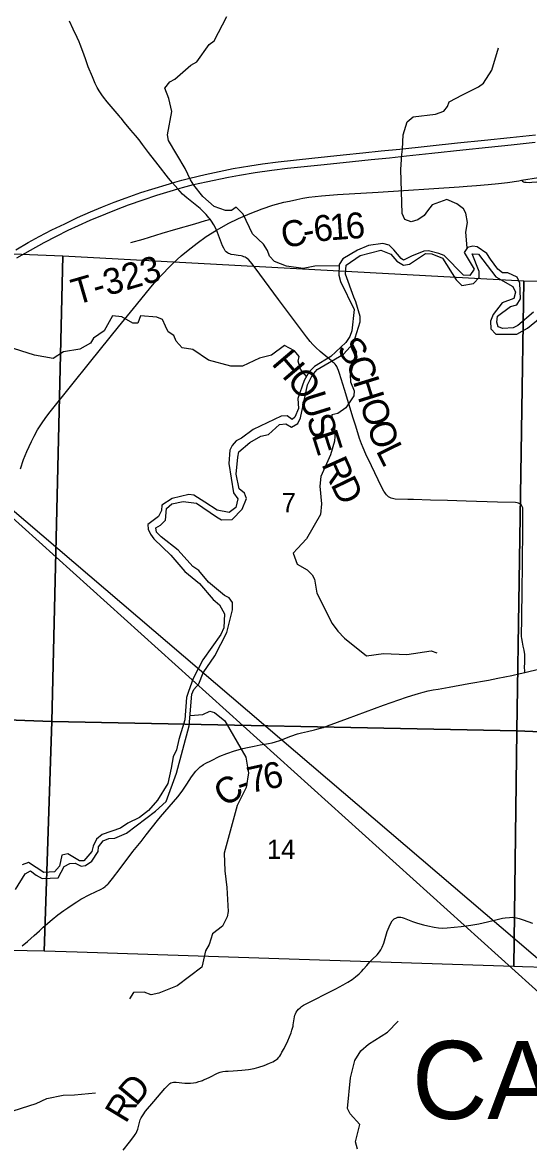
# Model space of a CAD drawing. Extents: x 0 to 34, y 0 to 22.
# Drawn here: x 6.991 to 8.096, y 18.295 to 20.748 of the extents above; entities that cross this region are included whole.
import ezdxf

# ---------------------------------------------------------------- set-up
doc = ezdxf.new("R2010")
doc.units = 0
for name, color, linetype in [('GM_X_County_Road', 7, 'Continuous'), ('GM_X_County_Road_Text', 7, 'Continuous'), ('GM_X_Minor_River', 7, 'Continuous'), ('GM_X_Section', 7, 'Continuous'), ('GM_X_Section_Text', 7, 'Continuous'), ('GM_X_State_Route', 7, 'Continuous'), ('GM_X_Township_Road', 7, 'Continuous'), ('GM_X_Township_Road_Text', 7, 'Continuous'), ('GM_X_Township_Text', 7, 'Continuous'), ('SH_Data', 7, 'Continuous')]:
    doc.layers.add(name, color=color, linetype=linetype)

msp = doc.modelspace()

# ---------------------------------------------------------------- linework, layer by layer
at = {"layer": 'GM_X_County_Road'}
for points in [[(8.0813, 20.4027), (8.1179, 20.4089), (8.2717, 20.437)], [(7.4149, 20.2934), (7.4164, 20.2943), (7.4408, 20.308), (7.463, 20.319), (7.4885, 20.3302), (7.5146, 20.3403), (7.5381, 20.348), (7.5621, 20.3545), (7.5743, 20.3574), (7.5902, 20.3608), (7.6034, 20.3633), (7.6168, 20.3655), (7.6445, 20.3688), (7.6789, 20.3714), (7.768, 20.3769), (7.9451, 20.3883), (7.9621, 20.3895), (7.9824, 20.391), (8.0083, 20.3934), (8.0305, 20.3958), (8.0504, 20.3982), (8.075, 20.4016), (8.0813, 20.4027)], [(6.9871, 19.7721), (6.9939, 19.7927), (7.0007, 19.81), (7.0108, 19.8316), (7.017, 19.8436), (7.0246, 19.8575), (7.0328, 19.8706), (7.0427, 19.8843), (7.0518, 19.8967), (7.1409, 20.0073), (7.2011, 20.0825), (7.2405, 20.1305), (7.2719, 20.169), (7.288, 20.1878), (7.2986, 20.1992), (7.31, 20.2112), (7.3199, 20.2208), (7.3294, 20.2298), (7.3378, 20.2372), (7.3457, 20.2441), (7.3594, 20.2549), (7.3726, 20.2651), (7.3928, 20.2795), (7.4149, 20.2934)], [(6.991, 18.7293), (7.0024, 18.7392), (7.0173, 18.7522), (7.0285, 18.7626), (7.0369, 18.7701), (7.0559, 18.7869), (7.0684, 18.7973), (7.0816, 18.8069), (7.0904, 18.8129), (7.1001, 18.8191), (7.11, 18.8255), (7.119, 18.8312), (7.1382, 18.8414), (7.1633, 18.8536), (7.1681, 18.8565), (7.1717, 18.8589), (7.1745, 18.8613), (7.1775, 18.8643), (7.1792, 18.8661), (7.1878, 18.8764), (7.2049, 18.8985), (7.2327, 18.9359), (7.2503, 18.9576), (7.2617, 18.9719), (7.2863, 19.0037), (7.2929, 19.0117), (7.3023, 19.0227), (7.331, 19.0554), (7.3404, 19.0676), (7.3506, 19.0831), (7.3607, 19.0988), (7.37, 19.1113), (7.3726, 19.1144), (7.3765, 19.1181), (7.3795, 19.1208), (7.3838, 19.124), (7.3869, 19.126), (7.3918, 19.1288), (7.4028, 19.1342), (7.4226, 19.1437), (7.4376, 19.15), (7.4545, 19.156), (7.4725, 19.1609), (7.4826, 19.1633), (7.497, 19.166), (7.5105, 19.1685), (7.5285, 19.1717), (7.5363, 19.1734), (7.544, 19.1754), (7.5531, 19.1785), (7.577, 19.1879), (7.5917, 19.1927), (7.6008, 19.1953), (7.6134, 19.1983), (7.629, 19.2016), (7.6338, 19.2028), (7.6419, 19.2049), (7.6485, 19.207), (7.6577, 19.21), (7.7013, 19.2263), (7.7799, 19.2553), (7.8297, 19.2727), (7.8415, 19.2766), (7.8564, 19.2811), (7.8661, 19.2838), (7.8775, 19.2865), (7.8879, 19.2888), (7.8989, 19.2907), (7.9234, 19.2948), (7.9661, 19.3026), (8.0088, 19.3105), (8.029, 19.3145), (8.0601, 19.3207), (8.078, 19.3248), (8.0885, 19.3272)], [(8.0885, 19.3272), (8.1209, 19.3346)]]:
    msp.add_lwpolyline(points, dxfattribs=at)
at = {"layer": 'GM_X_Minor_River'}
for points in [[(7.683, 20.2154), (7.6294, 20.2153), (7.6044, 20.2099), (7.5677, 20.2147), (7.5416, 20.2252), (7.5305, 20.2366), (7.5263, 20.2491), (7.5179, 20.2627), (7.4936, 20.2857), (7.473, 20.3285), (7.4581, 20.3437), (7.4476, 20.3364), (7.4347, 20.3367), (7.4101, 20.3454), (7.385, 20.3669), (7.3659, 20.3923), (7.358, 20.404), (7.3465, 20.4286), (7.3103, 20.4896), (7.3083, 20.5021), (7.3176, 20.5533), (7.311, 20.5814), (7.3022, 20.6037), (7.3135, 20.6182), (7.3244, 20.6239), (7.3591, 20.6544), (7.3724, 20.6613), (7.3994, 20.6993), (7.41, 20.7073), (7.4374, 20.7605)], [(7.9627, 20.255), (7.9595, 20.289), (7.9628, 20.3102), (7.9594, 20.3307), (7.954, 20.3405), (7.94, 20.3515), (7.9183, 20.3609), (7.8858, 20.349), (7.8761, 20.3361), (7.8685, 20.3254), (7.8549, 20.3163), (7.8402, 20.3121), (7.8266, 20.3173), (7.8204, 20.3302), (7.8174, 20.4265), (7.8199, 20.4592), (7.821, 20.4706), (7.8227, 20.5017), (7.8313, 20.5302), (7.8445, 20.5416), (7.8929, 20.5471), (7.9111, 20.5536), (7.9194, 20.5639), (7.9231, 20.5741), (7.9522, 20.5898), (7.9869, 20.607), (7.9982, 20.615), (8.0163, 20.6435), (8.0305, 20.6921)], [(8.1071, 20.1146), (8.0728, 20.0853), (8.063, 20.0803), (8.0403, 20.0787), (8.0304, 20.0821), (8.027, 20.0923), (8.0288, 20.106), (8.0567, 20.127), (8.0711, 20.1304), (8.079, 20.1434), (8.077, 20.1779), (8.0716, 20.1911), (8.0508, 20.2002), (8.0398, 20.2005), (8.0291, 20.2084), (8.0135, 20.2304), (8.0055, 20.2425), (7.9843, 20.2572), (7.9748, 20.2587), (7.9631, 20.2556), (7.9559, 20.2446), (7.9773, 20.2082), (7.9683, 20.1949), (7.9546, 20.1952), (7.9121, 20.2383), (7.9007, 20.2425), (7.8776, 20.2488), (7.8677, 20.248), (7.8405, 20.2369), (7.8236, 20.2279), (7.818, 20.2317), (7.8026, 20.2505), (7.792, 20.2607), (7.778, 20.2644), (7.7466, 20.2605), (7.7228, 20.2498)], [(6.9763, 18.8525), (6.9973, 18.8871), (7.0087, 18.8936), (7.0216, 18.8837), (7.0341, 18.8766), (7.0694, 18.8785), (7.0824, 18.9029), (7.0949, 18.9098), (7.1063, 18.9102), (7.1195, 18.9034), (7.1294, 18.9054), (7.1426, 18.9149), (7.1569, 18.9354), (7.1576, 18.9457), (7.1674, 18.959), (7.1802, 18.9643), (7.1931, 18.9648), (7.2184, 18.9759), (7.2822, 19.0235), (7.3055, 19.0448), (7.328, 19.1068), (7.3555, 19.2101), (7.3609, 19.2795), (7.3654, 19.2901), (7.3763, 19.3023), (7.3857, 19.3263), (7.4117, 19.3632), (7.4379, 19.4141), (7.4502, 19.4638), (7.4501, 19.4798), (7.4425, 19.49), (7.4323, 19.4953), (7.3977, 19.5247), (7.3768, 19.5497), (7.3635, 19.5584), (7.3316, 19.5943), (7.2939, 19.6237), (7.2841, 19.6336), (7.2825, 19.6434), (7.2931, 19.6488), (7.304, 19.6595), (7.3062, 19.6856), (7.3175, 19.6955), (7.3421, 19.7006), (7.3712, 19.6969), (7.4149, 19.6674), (7.4263, 19.6606), (7.449, 19.6611), (7.4708, 19.6836), (7.4806, 19.7075), (7.476, 19.7185), (7.4642, 19.7283), (7.458, 19.7602), (7.462, 19.7974), (7.4635, 19.8091), (7.488, 19.8293), (7.5118, 19.8434), (7.5284, 19.8473), (7.5529, 19.8686), (7.5662, 19.8702), (7.5787, 19.863), (7.593, 19.8711), (7.5987, 19.8836), (7.6135, 19.9555), (7.6241, 19.9763), (7.6347, 19.9892), (7.6927, 20.0228), (7.7142, 20.0464), (7.7287, 20.0935), (7.7287, 20.1049), (7.7195, 20.1367), (7.7152, 20.1469), (7.6965, 20.1977), (7.6983, 20.2171), (7.7285, 20.2384), (7.7739, 20.2496), (7.7955, 20.2413), (7.8088, 20.2262), (7.8236, 20.2168)], [(6.9763, 18.8525), (6.9973, 18.8871), (7.0087, 18.8936), (7.0216, 18.8837), (7.0341, 18.8766), (7.0694, 18.8785), (7.0824, 18.9029), (7.0949, 18.9098), (7.1063, 18.9102), (7.1195, 18.9034), (7.1294, 18.9054), (7.1426, 18.9149), (7.1569, 18.9354), (7.1576, 18.9457), (7.1674, 18.959), (7.1802, 18.9643), (7.1931, 18.9648), (7.2184, 18.9759), (7.2822, 19.0235), (7.3055, 19.0448), (7.328, 19.1068), (7.3555, 19.2101), (7.3609, 19.2795), (7.3654, 19.2901), (7.3763, 19.3023), (7.3857, 19.3263), (7.4117, 19.3632), (7.4379, 19.4141), (7.4502, 19.4638), (7.4501, 19.4798), (7.4425, 19.49), (7.4323, 19.4953), (7.3977, 19.5247), (7.3768, 19.5497), (7.3635, 19.5584), (7.3316, 19.5943), (7.2939, 19.6237), (7.2841, 19.6336), (7.2825, 19.6434), (7.2931, 19.6488), (7.304, 19.6595), (7.3062, 19.6856), (7.3175, 19.6955), (7.3421, 19.7006), (7.3712, 19.6969), (7.4149, 19.6674), (7.4263, 19.6606), (7.449, 19.6611), (7.4708, 19.6836), (7.4806, 19.7075), (7.476, 19.7185), (7.4642, 19.7283), (7.458, 19.7602), (7.462, 19.7974), (7.4635, 19.8091), (7.488, 19.8293), (7.5118, 19.8434), (7.5284, 19.8473), (7.5529, 19.8686), (7.5662, 19.8702), (7.5787, 19.863), (7.593, 19.8711), (7.5987, 19.8836), (7.6135, 19.9555), (7.6241, 19.9763), (7.6347, 19.9892), (7.6927, 20.0228), (7.7142, 20.0464), (7.7287, 20.0935), (7.7287, 20.1049), (7.7195, 20.1367), (7.7152, 20.1469), (7.6965, 20.1977), (7.6983, 20.2171), (7.7285, 20.2384), (7.7739, 20.2496), (7.7955, 20.2413), (7.8088, 20.2262), (7.8236, 20.2168)], [(7.7228, 20.2498), (7.6907, 20.2311), (7.6831, 20.2189), (7.6821, 20.1954), (7.6856, 20.1814), (7.7154, 20.12), (7.7106, 20.0733), (7.7065, 20.0615), (7.6971, 20.0479), (7.6646, 20.0174), (7.6292, 19.9956), (7.6172, 19.9842), (7.6063, 19.9648), (7.5924, 19.9257), (7.594, 19.9041), (7.5862, 19.885), (7.5801, 19.8801), (7.5691, 19.888), (7.5563, 19.8869), (7.4954, 19.8582), (7.4698, 19.8387), (7.4581, 19.8334), (7.4494, 19.8231), (7.4442, 19.8128), (7.442, 19.7836), (7.4521, 19.7195), (7.4617, 19.7063), (7.4572, 19.6873), (7.4429, 19.6766), (7.4163, 19.6815), (7.3894, 19.6992), (7.3655, 19.7143), (7.3545, 19.7162), (7.3182, 19.7073), (7.2959, 19.6928), (7.2948, 19.681), (7.2885, 19.6681), (7.2654, 19.6502), (7.2659, 19.64), (7.2708, 19.6294), (7.2781, 19.6188), (7.3157, 19.5836), (7.3458, 19.5473), (7.3777, 19.5216), (7.4077, 19.4864), (7.4214, 19.4751), (7.4325, 19.4554), (7.4311, 19.4243), (7.4247, 19.4102), (7.3852, 19.3547), (7.3638, 19.3137), (7.3537, 19.2855), (7.3492, 19.2726), (7.346, 19.2233), (7.3326, 19.1805), (7.3278, 19.1576), (7.3204, 19.1427), (7.3158, 19.1177), (7.3088, 19.0843), (7.2866, 19.0482), (7.2666, 19.025), (7.247, 19.0097), (7.2213, 18.9979), (7.2055, 18.9868), (7.1654, 18.973), (7.153, 18.9624), (7.1455, 18.9471), (7.1429, 18.9354), (7.1255, 18.9152), (7.1163, 18.9152), (7.0903, 18.9306), (7.0774, 18.9276), (7.0726, 18.904), (7.0613, 18.8911), (7.0378, 18.8895), (7.0044, 18.9117), (6.9908, 18.9068)], [(7.8236, 20.2168), (7.8361, 20.2191), (7.8712, 20.2424), (7.8855, 20.2417), (7.9083, 20.2323), (7.938, 20.1849), (7.9509, 20.1729), (7.9763, 20.1771), (7.9883, 20.1904), (7.9887, 20.203), (7.9734, 20.242), (7.9874, 20.2409), (8.0251, 20.1917), (8.0622, 20.1706), (8.068, 20.1581), (8.0642, 20.1444), (8.0385, 20.1352), (8.019, 20.109), (8.0134, 20.0949), (8.0138, 20.0779), (8.0248, 20.0665), (8.0706, 20.0667), (8.0941, 20.0793), (8.122, 20.1022)], [(7.6114, 19.974), (7.5982, 19.9898), (7.5932, 20.0073), (7.5958, 20.0179), (7.5855, 20.03), (7.5635, 20.0417), (7.5349, 20.0207), (7.5092, 20.0142), (7.4718, 19.9966), (7.4464, 19.9961), (7.3975, 20.0092), (7.3637, 20.0326), (7.3399, 20.0367), (7.3273, 20.0511), (7.322, 20.0632), (7.3098, 20.0715), (7.3037, 20.084), (7.2968, 20.0984), (7.2847, 20.1033), (7.2491, 20.1062), (7.2431, 20.0906), (7.2325, 20.0902), (7.2082, 20.1041), (7.1881, 20.1067), (7.1701, 20.074), (7.1463, 20.0576), (7.1396, 20.047), (7.1165, 20.0336), (7.081, 20.0278), (7.0587, 20.0129), (7.0178, 20.0208), (6.9583, 20.0391)], [(7.7123, 20.0443), (7.7206, 20.0277), (7.7068, 19.9768), (7.708, 19.962), (7.7157, 19.9424), (7.7146, 19.9314), (7.6973, 19.9055), (7.6799, 19.8933), (7.667, 19.8902), (7.6678, 19.8803), (7.6744, 19.853), (7.673, 19.8325), (7.664, 19.8025), (7.643, 19.7554), (7.6408, 19.7341), (7.6441, 19.6958), (7.6423, 19.6719), (7.6114, 19.6187), (7.5918, 19.5981), (7.5828, 19.5874), (7.5912, 19.5636), (7.6129, 19.5515), (7.6243, 19.5406), (7.6293, 19.5307), (7.634, 19.5004), (7.6676, 19.4338), (7.6798, 19.4171), (7.6947, 19.4017), (7.7426, 19.3632), (7.7797, 19.3683), (7.8309, 19.3666), (7.8835, 19.3745), (7.8964, 19.3696)], [(7.3573, 19.2326), (7.3854, 19.2348), (7.4002, 19.2421), (7.4104, 19.2395), (7.4336, 19.221), (7.4791, 19.1416), (7.483, 19.1203), (7.4849, 19.1074), (7.4798, 19.0755), (7.4603, 19.036), (7.4319, 18.9323), (7.4329, 18.8936), (7.4376, 18.8568), (7.4405, 18.8049), (7.4386, 18.7931), (7.4285, 18.7722), (7.4062, 18.7554), (7.3991, 18.7322), (7.3908, 18.7189), (7.3849, 18.6927), (7.3827, 18.6832)], [(7.3827, 18.6832), (7.3294, 18.642), (7.2893, 18.6263), (7.2723, 18.6228), (7.2571, 18.628), (7.234, 18.6272), (7.2253, 18.6138)], [(7.7226, 18.2849), (7.7183, 18.3008), (7.728, 18.3392), (7.7071, 18.3622), (7.7013, 18.374), (7.7078, 18.4408), (7.7171, 18.4788), (7.7299, 18.4997), (7.7469, 18.5146), (7.7885, 18.5406), (7.8119, 18.5649)], [(6.3977, 18.2296), (6.4186, 18.2279), (6.4369, 18.2086), (6.4495, 18.1836), (6.4761, 18.1773), (6.547, 18.1723), (6.5572, 18.1724), (6.5992, 18.1968), (6.6211, 18.217), (6.644, 18.2543), (6.6758, 18.2768), (6.7268, 18.3032), (6.7793, 18.3399), (6.8243, 18.3659), (6.8701, 18.374), (6.9066, 18.3628), (6.9191, 18.3613), (6.9551, 18.3638), (7.0213, 18.3846), (7.0444, 18.396), (7.0804, 18.403), (7.105, 18.4039), (7.1512, 18.4086)]]:
    msp.add_lwpolyline(points, dxfattribs=at)
at = {"layer": 'GM_X_Section'}
for points in [[(6.1908, 20.2736), (7.0795, 20.2374), (7.0553, 19.2199), (6.1559, 19.253), (6.1718, 19.7471), (6.1903, 20.2549), (6.1905, 20.2588)], [(7.0795, 20.2374), (8.0858, 20.1828), (8.0709, 19.1994), (7.0553, 19.2199)], [(8.0858, 20.1828), (8.5906, 20.172), (8.5904, 20.1552), (8.5847, 19.6569), (8.5803, 19.1784), (8.0709, 19.1994)], [(6.1559, 19.253), (7.0553, 19.2199), (7.0388, 18.7177), (6.6277, 18.7256), (6.1384, 18.7353), (6.1557, 19.2472)], [(7.0553, 19.2199), (8.0709, 19.1994), (8.0639, 18.6844), (7.5959, 18.6998), (7.1106, 18.7154), (7.0388, 18.7177)], [(8.0709, 19.1994), (8.5803, 19.1784), (8.5708, 18.6694), (8.083, 18.6836), (8.0639, 18.6844)]]:
    msp.add_lwpolyline(points, close=True, dxfattribs=at)
at = {"layer": 'GM_X_State_Route'}
for points in [[(6.9768, 20.2509), (7.0037, 20.2664), (7.0282, 20.2798), (7.0557, 20.2941), (7.0836, 20.3078), (7.1116, 20.321), (7.14, 20.3336), (7.1658, 20.3444), (7.1917, 20.3548), (7.2179, 20.3645), (7.2501, 20.3758), (7.2737, 20.3835), (7.3124, 20.3952), (7.319, 20.3971), (7.3392, 20.4029), (7.3572, 20.4076), (7.3904, 20.4156), (7.4208, 20.4222), (7.4512, 20.4282), (7.4879, 20.4345), (7.5156, 20.4386), (7.5494, 20.4429), (7.6235, 20.4512), (7.6915, 20.4582), (7.7347, 20.4627), (7.7749, 20.4668), (7.815, 20.471), (7.9416, 20.4843), (8.0003, 20.4904), (8.0559, 20.4963), (8.1115, 20.5023)], [(6.979, 20.2329), (7.0086, 20.2499), (7.0385, 20.2665), (7.066, 20.2809), (7.091, 20.2934), (7.1135, 20.304), (7.1391, 20.3153), (7.1735, 20.3296), (7.1966, 20.3389), (7.2228, 20.3487), (7.255, 20.3601), (7.2845, 20.3699), (7.3142, 20.3791), (7.3303, 20.3838), (7.3411, 20.3869), (7.3651, 20.3932), (7.3924, 20.3994), (7.441, 20.4096), (7.4655, 20.4142), (7.4992, 20.4197), (7.5361, 20.4249), (7.5701, 20.429), (7.6504, 20.4373), (7.7122, 20.4438), (7.7524, 20.4479), (7.7925, 20.452), (7.8296, 20.4558), (7.8852, 20.4617), (7.9531, 20.4691), (8.0087, 20.4749), (8.0581, 20.4803), (8.1106, 20.4859)]]:
    msp.add_lwpolyline(points, dxfattribs=at)
at = {"layer": 'GM_X_Township_Road'}
for points in [[(7.4009, 20.3175), (7.3986, 20.3207), (7.3926, 20.3278), (7.3862, 20.3346), (7.3792, 20.3407), (7.3647, 20.3524), (7.3502, 20.3641), (7.3409, 20.3722), (7.3303, 20.3838), (7.319, 20.3971), (7.3105, 20.4074), (7.2874, 20.4366), (7.2665, 20.4636), (7.2535, 20.4811), (7.2459, 20.4909), (7.238, 20.5004), (7.228, 20.5122), (7.2142, 20.5289), (7.2066, 20.5385), (7.2047, 20.5409), (7.2029, 20.5433), (7.1767, 20.5738), (7.1687, 20.584), (7.1646, 20.5897), (7.159, 20.598), (7.1546, 20.6055), (7.1503, 20.6144), (7.1446, 20.6286), (7.1352, 20.6507), (7.1288, 20.6682), (7.123, 20.6845), (7.1174, 20.6992), (7.115, 20.7053), (7.1106, 20.7147), (7.1018, 20.7331), (7.0943, 20.7501)], [(8.0813, 20.4027), (8.0832, 20.4005), (8.085, 20.3994), (8.0873, 20.3989), (8.0912, 20.3985), (8.0976, 20.3981), (8.1038, 20.3983), (8.1594, 20.4019), (8.181, 20.4025), (8.1995, 20.4033), (8.2119, 20.4042), (8.2233, 20.4052), (8.2301, 20.4061), (8.2365, 20.4073), (8.2484, 20.4106), (8.2573, 20.4133), (8.2689, 20.4175), (8.2975, 20.429), (8.333, 20.4413), (8.3385, 20.4439), (8.34, 20.4452), (8.3413, 20.447), (8.3426, 20.4502)], [(7.2281, 20.267), (7.2549, 20.2743), (7.2963, 20.2869), (7.326, 20.2956), (7.3676, 20.3077), (7.3913, 20.3147), (7.3972, 20.3164), (7.4009, 20.3175)], [(7.4149, 20.2934), (7.4133, 20.297), (7.4089, 20.3052), (7.404, 20.3131), (7.4009, 20.3175)], [(8.0885, 19.3272), (8.0883, 19.3296), (8.0878, 19.3386), (8.0881, 19.3479), (8.0886, 19.3572), (8.0884, 19.3634), (8.088, 19.3664), (8.0866, 19.3756), (8.0847, 19.3847), (8.0831, 19.3935), (8.0818, 19.4009), (8.0812, 19.4053), (8.0808, 19.4122), (8.0813, 19.4215), (8.0817, 19.4308), (8.0816, 19.4432), (8.082, 19.4556), (8.0827, 19.499), (8.0841, 19.6387), (8.0838, 19.6541), (8.0839, 19.6634), (8.084, 19.6821), (8.084, 19.6851), (8.0838, 19.6869), (8.0834, 19.6881), (8.0828, 19.6897), (8.082, 19.691), (8.08, 19.6933), (8.0774, 19.6954), (8.0747, 19.6969), (8.0717, 19.6977), (8.0678, 19.6981), (8.0283, 19.6991), (7.9601, 19.7012), (7.9197, 19.7026), (7.8825, 19.7038), (7.8453, 19.7049), (7.8329, 19.705), (7.805, 19.7056), (7.802, 19.7062), (7.799, 19.7071), (7.7961, 19.7082), (7.7934, 19.7096), (7.7908, 19.7112), (7.7884, 19.7132), (7.7862, 19.7154), (7.7842, 19.7178), (7.7824, 19.7203), (7.7807, 19.7229), (7.7777, 19.7283), (7.7683, 19.7479), (7.7534, 19.7787), (7.7412, 19.8038), (7.735, 19.818), (7.7316, 19.8267), (7.7275, 19.8384), (7.7193, 19.865), (7.7137, 19.8828), (7.6946, 19.9451), (7.6837, 19.9807), (7.6816, 19.9866), (7.6794, 19.9922), (7.6777, 19.9958), (7.6762, 19.9982), (7.6738, 20.001), (7.6719, 20.0029), (7.6698, 20.0046), (7.6652, 20.0087), (7.658, 20.0147), (7.6414, 20.0286), (7.6322, 20.037), (7.6256, 20.0436), (7.6195, 20.0506), (7.6117, 20.0602), (7.5875, 20.0926), (7.5504, 20.1424), (7.5097, 20.1972), (7.4951, 20.2173), (7.4894, 20.2247), (7.4851, 20.2292), (7.4827, 20.2311), (7.4802, 20.2329), (7.4775, 20.2343), (7.4746, 20.2355), (7.4717, 20.2365), (7.4687, 20.2373), (7.4626, 20.2384), (7.4534, 20.2396), (7.4473, 20.2408), (7.4443, 20.2417), (7.4415, 20.2429), (7.4388, 20.2444), (7.4364, 20.2464), (7.4343, 20.2487), (7.4326, 20.2512), (7.4311, 20.254), (7.4284, 20.2596), (7.4239, 20.2711), (7.4171, 20.2885), (7.4149, 20.2934)], [(7.2114, 18.2832), (7.2249, 18.3002), (7.2345, 18.3131), (7.2377, 18.3174), (7.2396, 18.3203), (7.2414, 18.3236), (7.2435, 18.3288), (7.245, 18.3347), (7.2472, 18.3436), (7.2487, 18.3492), (7.2503, 18.3533), (7.2517, 18.3559), (7.2547, 18.3605), (7.2603, 18.3679), (7.2782, 18.3894), (7.3022, 18.4178), (7.3063, 18.4223), (7.3107, 18.4265), (7.3131, 18.4283), (7.3157, 18.4298), (7.3184, 18.4309), (7.3213, 18.4315), (7.3243, 18.4317), (7.3273, 18.4316), (7.3459, 18.4296), (7.3521, 18.4293), (7.3584, 18.4295), (7.3646, 18.4301), (7.3707, 18.4311), (7.3767, 18.4327), (7.3795, 18.4336), (7.3821, 18.4345), (7.3844, 18.4353), (7.3869, 18.4363), (7.3923, 18.4387), (7.4007, 18.4427), (7.4173, 18.4511), (7.4234, 18.4533), (7.429, 18.4548), (7.4347, 18.4555), (7.4408, 18.4558), (7.4513, 18.4562), (7.4705, 18.4576), (7.4847, 18.4595), (7.4974, 18.4617), (7.5078, 18.464), (7.5189, 18.468), (7.531, 18.4728), (7.5381, 18.4761), (7.544, 18.4794), (7.5463, 18.481), (7.5488, 18.4834), (7.5511, 18.486), (7.5532, 18.4886), (7.5552, 18.492), (7.5579, 18.497), (7.5625, 18.5052), (7.571, 18.5218), (7.5747, 18.5303), (7.5784, 18.5392), (7.5799, 18.5451), (7.5822, 18.5541), (7.5828, 18.5571), (7.5856, 18.5746), (7.5864, 18.5779), (7.5872, 18.5808), (7.5889, 18.5842), (7.5909, 18.5875), (7.5942, 18.5913), (7.5974, 18.5942), (7.6005, 18.5967), (7.6053, 18.5995), (7.6286, 18.6115), (7.6368, 18.616), (7.645, 18.6204), (7.6754, 18.6359), (7.6917, 18.6445), (7.7016, 18.6503), (7.7112, 18.6563), (7.7186, 18.6618), (7.7263, 18.6683), (7.7315, 18.6732), (7.7358, 18.6782), (7.7432, 18.6866), (7.75, 18.6947), (7.7559, 18.7005), (7.7655, 18.7101), (7.7707, 18.7163), (7.7741, 18.7211), (7.7768, 18.7267), (7.7803, 18.7355), (7.788, 18.761), (7.7917, 18.7713), (7.7955, 18.7792), (7.7989, 18.7842), (7.8018, 18.7873), (7.8033, 18.7883), (7.8046, 18.7892), (7.8064, 18.7903), (7.8094, 18.7916), (7.811, 18.792), (7.8128, 18.7922), (7.8151, 18.7924), (7.8178, 18.7921), (7.8208, 18.7913), (7.8246, 18.79), (7.843, 18.7826), (7.8538, 18.7792), (7.8673, 18.7753), (7.8764, 18.7729), (7.8903, 18.77), (7.8999, 18.7686), (7.9092, 18.7682), (7.9186, 18.7686), (7.9496, 18.7716), (7.9704, 18.7746), (7.9879, 18.7777), (8.0067, 18.7818), (8.0217, 18.7856), (8.0305, 18.7876), (8.0394, 18.7897), (8.0455, 18.7906), (8.0547, 18.7917), (8.0608, 18.792), (8.0638, 18.7917), (8.0698, 18.7906), (8.0758, 18.7891), (8.0846, 18.7863), (8.1049, 18.7788)]]:
    msp.add_lwpolyline(points, dxfattribs=at)
at = {"layer": 'SH_Data'}
msp.add_lwpolyline([(6.619, 19.9811), (10.5909, 16.3957), (10.5909, 16.5853)], close=True, dxfattribs=at)

# ---------------------------------------------------------------- texts
at = {"layer": 'GM_X_County_Road_Text'}
for s, rotation, p in [('6', 4.0103, (7.699, 20.274)), ('C', 13.6926, (7.5635, 20.2527)), ('6', 6.2465, (7.6298, 20.2678)), ('1', 4.1564, (7.6641, 20.2715)), ('-', 10.7649, (7.6081, 20.2636)), ('6', 11.0119, (7.5229, 19.0705)), ('7', 12.4735, (7.4891, 19.063)), ('C', 34.3298, (7.4337, 19.0312)), ('-', 19.2422, (7.4687, 19.0558))]:
    msp.add_text(s, height=0.0568, rotation=rotation, dxfattribs=at).set_placement(p)
at = {"layer": 'GM_X_Section_Text'}
for s, height, p in [('7', 0.0419, (7.5572, 19.6773)), ('14', 0.04186, (7.5252, 18.9196))]:
    msp.add_text(s, height=height, rotation=0, dxfattribs=at).set_placement(p)
at = {"layer": 'GM_X_Township_Road_Text'}
for s, height, rotation, p in [('T-323', 0.05682, 16.2706, (7.1082, 20.1297)), ('S', 0.0568, 309.2587, (7.6754, 20.0323)), ('H', 0.0568, 310.4231, (7.5335, 20.0014)), ('C', 0.0568, 289.4323, (7.6971, 20.0072)), ('O', 0.0568, 310.8319, (7.5662, 19.963)), ('H', 0.0568, 287.3451, (7.7124, 19.9637)), ('U', 0.0568, 287.4131, (7.5959, 19.9305)), ('O', 0.0568, 287.3503, (7.7274, 19.916)), ('S', 0.0568, 287.4123, (7.6109, 19.8828)), ('O', 0.0568, 289.0194, (7.7428, 19.8665)), ('E', 0.0568, 287.6493, (7.6224, 19.846)), ('L', 0.0568, 296.515, (7.7623, 19.8118)), ('R', 0.0568, 294.1319, (7.6434, 19.7824)), ('D', 0.0568, 295.8621, (7.6633, 19.7381)), ('D', 0.0568, 50.2672, (7.2398, 18.3776)), ('R', 0.0568, 58.8937, (7.217, 18.3395))]:
    msp.add_text(s, height=height, rotation=rotation, dxfattribs=at).set_placement(p)
at = {"layer": 'GM_X_Township_Text'}
msp.add_text('CASS', height=0.17045, rotation=0, dxfattribs=at).set_placement((7.8418, 18.3512))

doc.saveas('drawing.dxf')
